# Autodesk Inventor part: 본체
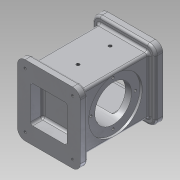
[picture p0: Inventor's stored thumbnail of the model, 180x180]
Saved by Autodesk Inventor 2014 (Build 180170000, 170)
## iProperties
Created: 2017-08
Part Number: 본체
Material: Aluminum 6061
Document SubType Name: Modeling
Designer: user
Density: 2.71 g/cm^3
Appearance: Aluminum - Flat
Mass: 905.247 g
Surface Area: 631.496 cm^2
Volume: 334.039 cm^3
Author: user
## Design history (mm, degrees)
sketch "Sketch1"
  geometry: L1 (-33, 0)-(-33, 37); L2 (-33, 37)-(33, 37); L3 (33, 37)-(33, -37); L4 (33, -37)-(-33, -37); L5 (-33, -37)-(-33, 0); 1 further point
  constraints: 10 end point
  dimensions: "d1" = 74 distance of L4.end L1.end; "d3" = 66 distance of L3.end L4.end; "d4" = 74 distance of L2.end L3.end; "d5" = 33 distance from line of L3 point (0, 0); "d6" = 37 distance from line of L4 point (0, 0); "d7" = 37 distance from line of L2 point (0, 0); "d8" = 37 vertical distance of point (0, 0) L3.end; "d9" = 33 distance from line of L1 point (0, 0)
extrude "Extrusion1" new body sketch "Sketch1" distance "d10" = 88; taper "d11" = 0 deg
sketch "Sketch2"
  geometry: L1 (41, 0)-(41, 46); L2 (41, 46)-(-41, 46); L3 (-41, 46)-(-41, -46); L4 (-41, -46)-(41, -46); L5 (41, -46)-(41, 0); 1 further point
  constraints: 10 end point
  dimensions: "d12" = 41 distance from line of L3 point (0, 0); "d13" = 41 distance from line of L1 point (0, 0); "d14" = 46 distance from line of L2 point (0, 0); "d15" = 46 distance from line of L4 point (0, 0); "d16" = 41 horizontal distance of point (0, 0) L3.end; "d17" = 41 distance from line of L5 point (0, 0); "d18" = 92 distance of L2.end L3.end; "d19" = 82 distance of L1.end L2.end; "d20" = 46 distance of L1.start L1.end; "d21" = 82 distance of L3.end L4.end
extrude "Extrusion2" join sketch "Sketch2" distance "d22" = 10; taper "d23" = 0 deg
sketch "Sketch3"
  geometry: L1 (-33, 37)-(33, 37) reference; L2 (33, 37)-(33, -37) reference; L3 (33, -37)-(-33, -37) reference; L4 (-33, -37)-(-33, 37) reference; L5 (-41, 46)-(41, 46) reference; L6 (-41, -46)-(-41, 46) reference; L7 (41, -46)-(-41, -46) reference; L8 (41, 46)-(41, -46) reference; 1 further point
extrude "Extrusion3" join sketch "Sketch3" distance "d24" = 10; taper "d25" = 0 deg
sketch "Sketch5"
  geometry: L1 (41, 98)-(-41, 98) reference; L2 (41, 0)-(-41, 0) reference; L3 (41, 0)-(41, -10) reference; L4 (-41, -10)-(41, -10) reference; L5 (-41, 0)-(-41, -10) reference; L6 (33, 0)-(33, 88) reference; L7 (-33, 0)-(-33, 88) reference; L8 (33, 44)-(-33, 44); L9 (33, 44)-(33, 79); L10 (33, 79)-(30, 79); L11 (30, 68)-(22, 68); L12 (-33, 44)-(-33, 79); L13 (-33, 79)-(-30, 79); L14 (-30, 79)-(-30, 68); L15 (-30, 68)-(-22, 68); L16 (-22, 68)-(22, 68); L17 (30, 79)-(30, 68); 1 further point
  constraints: 20 end point, 2 midpoint, 2 point on line
  dimensions: "d26" = 70 diameter of L12.end L8; "d27" = 70 diameter of L10 L8; "d28" = 48 diameter of L16 L8; "d29" = 3 distance of L12.end L13.end; "d30" = 3 distance of L9.end L10.end; "d31" = 8 distance of L11.start L11.end; "d32" = 8 distance of L14.end L15.end; "d33" = 11 distance of L13.end L14.end; "d35" = 44 distance of L15.end L11.end; "d36" = 11 distance of L10.end L11.start; "d37" = 60 distance of L11.start L14.end; "d38" = 24 vertical distance of L11.start L8.start
revolve "Revolution1" sketch "Sketch5" stored, may be unused: angle "d39" = 90 deg
sketch "Sketch6"
  geometry: L1 (0, 0)-(24, 0); L2 (24, 0)-(24, 24); L3 (24, 24)-(-24, 24); L4 (-24, 24)-(-24, -24); L5 (-24, -24)-(24, -24); L6 (24, -24)-(24, 0); L7 (0, 0)-(0, 24); L8 (0, 0)-(0, 24); L9 (-33, -37)-(33, -37) reference; L10 (-33, 37)-(-33, -37) reference
  constraints: 16 end point, 1 midpoint
  dimensions: "d41" = 24 distance between parallel lines of L3 L1; "d42" = 48 distance between parallel lines of L3 L5; "d44" = 48 distance of L3.end L4.end; "d45" = 48 distance of L2.end L3.end; "d46" = 24 distance of L1.start L1.end; "d47" = 24 distance of L1.start L7.end; "d48" = 37 distance from line of L9 L1.start; "d49" = 24 horizontal distance of L1.start L4.end; "d50" = 48 distance of L4.end L5.end; "d51" = 33 distance from line of L10 L1.start
extrude "Extrusion4" cut sketch "Sketch6" distance "d52" = 16; taper "d53" = 0 deg
sketch "Sketch7"
  geometry: L1 (26, -26)-(-26, -26); L2 (-26, -26)-(-26, 26); L3 (-26, 26)-(26, 26); L4 (26, 26)-(26, -26); L5 (26, -26)-(-26, 26); L6 (-26, -26)-(26, 26); L7 (0, 0)-(0, 26); L8 (0, 0)-(26, 0)
  constraints: 16 end point, 4 midpoint
  dimensions: "d54" = 26 distance of L7.end L7.start; "d55" = 26 distance from line of L7.start L1; "d56" = 26 distance from line of L2 L7.start; "d57" = 26 distance from line of L4 L7.start; "d58" = 26 distance of L7.start L8.end
extrude "Extrusion5" cut sketch "Sketch7" distance "d59" = 8; taper "d60" = 0 deg
sketch "Sketch8"
  geometry: L1 (0, 0)-(22, 0); L2 (22, 0)-(22, 22); L3 (22, 22)-(-22, 22); L4 (-22, 22)-(-22, -22); L5 (-22, -22)-(22, -22); L6 (22, -22)-(22, 0); L7 (0, 0)-(0, 22); L8 (30, 35)-(30, -35) reference; L9 (-41, -46)-(41, -46) reference
  constraints: 14 end point, 1 midpoint
  dimensions: "d69" = 22 distance between parallel lines of L7 L4; "d70" = 22 distance of L1.start L7.end; "d71" = 22 distance from line of L2 L1.start; "d72" = 22 distance from line of L3 L1.start; "d73" = 22 distance from line of L5 L1.start; "d74" = 22 horizontal distance of L1.start L4.end; "d75" = 44 distance of L4.end L5.end; "d76" = 22 distance of L5.end L1.end; "d77" = 44 distance of L3.end L4.end; "d78" = 8 distance from line of L8 L1.end; "d112" = 46 distance from line of L9 L1.start
extrude "Extrusion6" cut sketch "Sketch8" distance "d79" = 82; taper "d80" = 0 deg
sketch "Sketch9"
  geometry: L1 (0, 29)-(0, -29); L2 (29, 0)-(-29, 0); L3 (46, -54)-(-46, -54) reference; C1 r 24 at (0, 0) reference; A1 r 29 centre (0, 0) between (0, 29) and (0, -29); 5 further points
  constraints: 5 coincident, 4 end point, 4 point on circle, 1 centre point
  dimensions: "d81" = 58 distance of L1.start L1.end; "d82" = 58 diameter of A1; "d83" = 58 distance of point (29, 0) point (-29, 0); "d84" = 29 horizontal distance of point (0, -29) point (-29, 0); "d85" = 25 distance from line of L3 point (0, -29)
hole "Hole1" sketch "Sketch9" diameter "d86" = 3.242; stored, may be unused: countersink angle "d90" = 90 deg, drill point angle "d92" = 118 deg; dims "d87" = 4, "d88" = 4, "d89" = 2, "d91" = 6
mirror "Mirror1"
workplane "Work Plane1"
sketch "Sketch11"
  geometry: L1 (8.272, 20.272)-(83.986, 20.272); L2 (83.986, 20.272)-(83.986, -9.196); L3 (83.986, -9.196)-(8.272, -9.196); L4 (8.272, -9.196)-(8.272, 20.272); 1 further point
  constraints: 2 other
emboss "Emboss1" sketch "Sketch11" dims "d97" = 0.5, "d98" = 0
sketch "Sketch12"
  geometry: L1 (0, 0)-(66, 0) reference; L2 (9, -98)-(57, -98) reference; L3 (33, -98)-(33, -60); L4 (33, -60)-(33, -18); 3 further points
  constraints: 4 end point, 2 coincident, 1 midpoint
  dimensions: "d99" = 38 distance of point (33, -60) L3.start; "d100" = 42 distance of L4.end L3.end; "d101" = 80 distance of point (33, -18) L3.start; "d102" = 18 distance from line of L1 point (33, -18)
hole "Hole2" sketch "Sketch12" at (33, -18), (33, -60) diameter "d103" = 4.134; stored, may be unused: countersink angle "d107" = 90 deg, drill point angle "d109" = 118 deg; dims "d104" = 15, "d105" = 4, "d106" = 2, "d108" = 15
fillet "Fillet1" dims "d110" = 3
fillet "Fillet2" dims "d111" = 3
fillet "Fillet3" dims "d113" = 3
fillet "Fillet4" dims "d114" = 3
fillet "Fillet5" dims "d115" = 3
fillet "Fillet6" dims "d116" = 3
fillet "Fillet7" dims "d117" = 10
fillet "Fillet8" dims "d118" = 10
hole "Hole3" diameter "d121" = 3.242; stored, may be unused: countersink angle "d125" = 90 deg, drill point angle "d127" = 118 deg; dims "d119" = 10, "d120" = 10, "d122" = 4, "d123" = 4, "d124" = 2, "d126" = 6
hole "Hole4" diameter "d130" = 3.242; stored, may be unused: countersink angle "d134" = 90 deg, drill point angle "d136" = 118 deg; dims "d128" = 10, "d129" = 10, "d131" = 4, "d132" = 4, "d133" = 2, "d135" = 6
hole "Hole5" diameter "d139" = 3.242; stored, may be unused: countersink angle "d143" = 90 deg, drill point angle "d145" = 118 deg; dims "d137" = 10, "d138" = 10, "d140" = 4, "d141" = 4, "d142" = 2, "d144" = 6
hole "Hole6" diameter "d148" = 3.242; stored, may be unused: countersink angle "d152" = 90 deg, drill point angle "d154" = 118 deg; dims "d146" = 10, "d147" = 10, "d149" = 4, "d150" = 4, "d151" = 2, "d153" = 6
hole "Hole7" diameter "d157" = 3.242; stored, may be unused: countersink angle "d161" = 90 deg, drill point angle "d163" = 118 deg; dims "d155" = 10, "d156" = 10, "d158" = 4, "d159" = 4, "d160" = 2, "d162" = 6
hole "Hole8" diameter "d166" = 3.242; stored, may be unused: countersink angle "d170" = 90 deg, drill point angle "d172" = 118 deg; dims "d164" = 10, "d165" = 10, "d167" = 4, "d168" = 4, "d169" = 2, "d171" = 6
hole "Hole9" diameter "d175" = 3.242; stored, may be unused: countersink angle "d179" = 90 deg, drill point angle "d181" = 118 deg; dims "d173" = 10, "d174" = 10, "d176" = 4, "d177" = 4, "d178" = 2, "d180" = 6
hole "Hole10" diameter "d184" = 3.242; stored, may be unused: countersink angle "d188" = 90 deg, drill point angle "d190" = 118 deg; dims "d182" = 10, "d183" = 10, "d185" = 4, "d186" = 4, "d187" = 2, "d189" = 6
fillet "Fillet10" dims "d192" = 3
fillet "Fillet13" dims "d195" = 3
fillet "Fillet14" dims "d196" = 3
chamfer "Chamfer1" distance "d197" = 1; stored, may be unused: second distance "d198" = 2, angle "d199" = 45 deg
body "Solid1"
node "Projected Loop1"
node "Project Cut Edges1"
